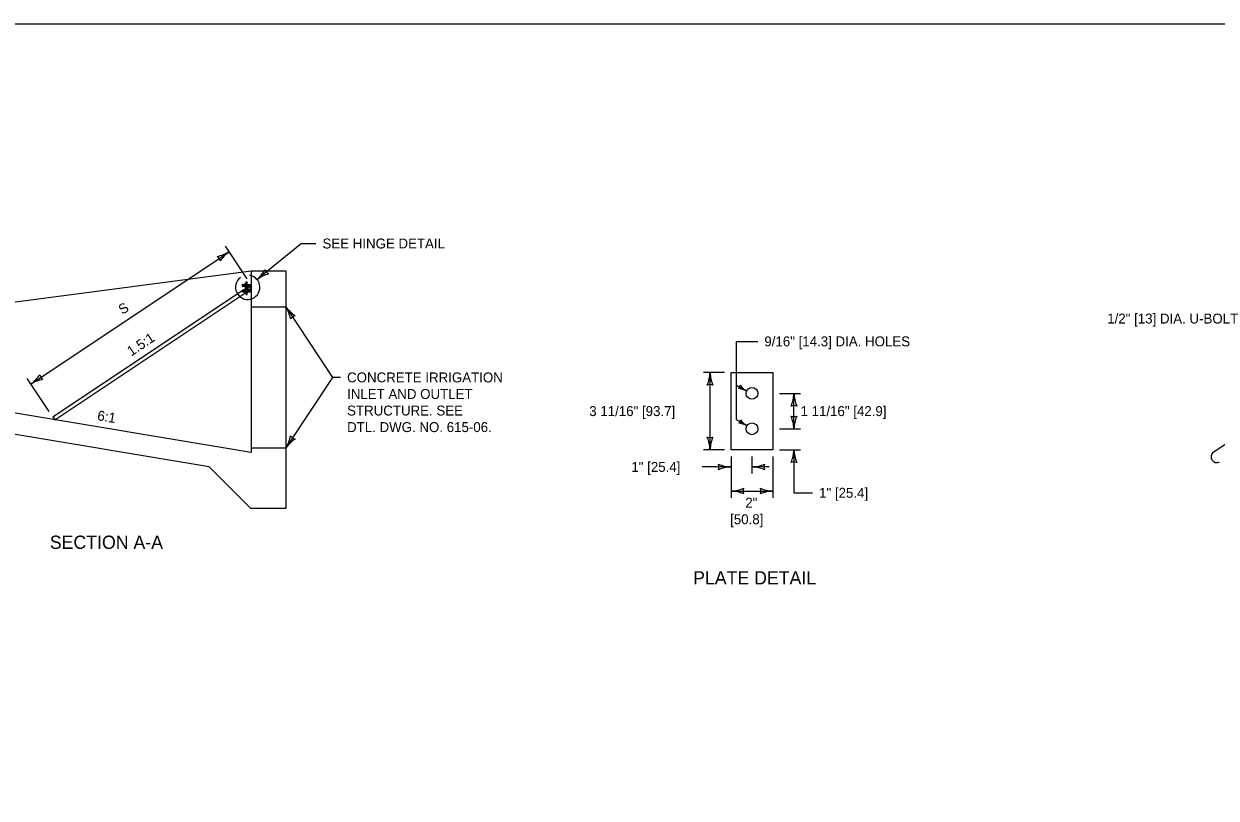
# Model space of a CAD drawing. Extents: x 49991.4 to 50021, y 49987.6 to 50011.4.
# Drawn here: x 50005.52 to 50012.72, y 49994.32 to 49999 of the extents above; entities that cross this region are included whole.
import ezdxf

# ---------------------------------------------------------------- set-up
doc = ezdxf.new("R2010")
doc.units = 0
for name, color, linetype in [('Level 1', 7, 'Continuous'), ('Level 2', 7, 'Continuous'), ('Level 3', 7, 'Continuous'), ('Level 4', 7, 'Continuous')]:
    doc.layers.add(name, color=color, linetype=linetype)

msp = doc.modelspace()

# ---------------------------------------------------------------- linework, layer by layer
at = {"layer": 'Level 1'}
for p, q in [((50005.12, 49997.2756), (50006.8919, 49997.5076)), ((50006.8919, 49997.5076), (50007.1028, 49997.5076)), ((50006.8919, 49997.5076), (50006.8919, 49996.4107)), ((50007.1028, 49997.5076), (50007.1028, 49996.0732)), ((50007.1028, 49997.5076), (50007.1028, 49996.0732)), ((50007.1028, 49997.5076), (50007.1028, 49996.0732)), ((50007.1028, 49997.5076), (50007.1028, 49996.0732)), ((50007.1028, 49997.5076), (50007.1028, 49996.0732)), ((50007.1028, 49997.5076), (50007.1028, 49996.0732)), ((50007.1028, 49997.5076), (50007.1028, 49996.0732)), ((50007.1028, 49997.5076), (50007.1028, 49996.0732)), ((50007.1028, 49997.5076), (50007.1028, 49996.0732)), ((50007.1028, 49997.5076), (50007.1028, 49996.0732)), ((50007.1028, 49997.5076), (50007.1028, 49996.0732)), ((50007.1028, 49997.5076), (50007.1028, 49996.0732)), ((50007.1028, 49997.5076), (50007.1028, 49996.0732)), ((50007.1028, 49997.5076), (50007.1028, 49996.0732)), ((50007.1028, 49997.5076), (50007.1028, 49996.0732)), ((50005.6946, 49996.6262), (50006.8391, 49997.3891)), ((50006.839, 49997.3902), (50006.8404, 49997.3916)), ((50006.839, 49997.3902), (50006.839, 49997.3825)), ((50006.8391, 49997.4246), (50006.8404, 49997.4259)), ((50006.8404, 49997.4259), (50006.8391, 49997.4246)), ((50006.8391, 49997.4246), (50006.8392, 49997.4167)), ((50006.8391, 49997.3891), (50006.8429, 49997.3916)), ((50006.8404, 49997.4259), (50006.8525, 49997.4259)), ((50006.8404, 49997.4259), (50006.8405, 49997.4154)), ((50006.8404, 49997.3916), (50006.8525, 49997.3916)), ((50006.8404, 49997.3916), (50006.8404, 49997.3811)), ((50006.8405, 49997.4154), (50006.8525, 49997.4154)), ((50006.8414, 49997.4246), (50006.8414, 49997.4167)), ((50006.8414, 49997.3902), (50006.8414, 49997.3825)), ((50006.8424, 49997.4259), (50006.8425, 49997.4154)), ((50006.8424, 49997.3916), (50006.8424, 49997.3811)), ((50006.8429, 49997.3916), (50006.8617, 49997.4041)), ((50006.8434, 49997.4246), (50006.8434, 49997.4167)), ((50006.8434, 49997.3902), (50006.8434, 49997.3825)), ((50006.8444, 49997.4259), (50006.8444, 49997.4154)), ((50006.8444, 49997.3916), (50006.8444, 49997.3811)), ((50006.8454, 49997.4246), (50006.8454, 49997.4167)), ((50006.8454, 49997.3902), (50006.8454, 49997.3825)), ((50006.8464, 49997.4259), (50006.8464, 49997.4154)), ((50006.8464, 49997.3916), (50006.8464, 49997.3811)), ((50006.8473, 49997.4246), (50006.8474, 49997.4167)), ((50006.8474, 49997.3902), (50006.8474, 49997.3825)), ((50006.8484, 49997.4259), (50006.8484, 49997.4154)), ((50006.8484, 49997.3916), (50006.8484, 49997.3811)), ((50006.8493, 49997.4246), (50006.8494, 49997.4167)), ((50006.8494, 49997.3825), (50006.8494, 49997.3902)), ((50006.8503, 49997.4259), (50006.8503, 49997.4154)), ((50006.8503, 49997.3916), (50006.8503, 49997.3811)), ((50006.8513, 49997.4246), (50006.8514, 49997.4167)), ((50006.8514, 49997.3825), (50006.8514, 49997.3902)), ((50006.8523, 49997.4259), (50006.8523, 49997.4154)), ((50006.8523, 49997.3916), (50006.8523, 49997.3811)), ((50006.8525, 49997.4149), (50006.8525, 49997.4268)), ((50006.8525, 49997.3799), (50006.8525, 49997.3926)), ((50006.8533, 49997.4298), (50006.8617, 49997.4298)), ((50006.8533, 49997.4246), (50006.8617, 49997.4246)), ((50006.8533, 49997.4167), (50006.8617, 49997.4167)), ((50006.8533, 49997.4114), (50006.8617, 49997.4114)), ((50006.8533, 49997.3956), (50006.8617, 49997.3956)), ((50006.8534, 49997.3903), (50006.8617, 49997.3903)), ((50006.8617, 49997.4035), (50006.8617, 49997.4424)), ((50006.8617, 49997.4424), (50006.8696, 49997.4424)), ((50006.8617, 49997.4114), (50006.8617, 49997.4298)), ((50006.8617, 49997.3646), (50006.8617, 49997.4035)), ((50006.8617, 49997.3771), (50006.8617, 49997.3956)), ((50006.8696, 49997.4035), (50006.8696, 49997.4424)), ((50006.8696, 49997.4259), (50006.8919, 49997.4259)), ((50006.8696, 49997.4154), (50006.8919, 49997.4154)), ((50006.8696, 49997.4093), (50006.8742, 49997.4124)), ((50006.8696, 49997.3646), (50006.8696, 49997.4035)), ((50006.8696, 49997.3916), (50006.8919, 49997.3916)), ((50006.8696, 49997.3916), (50006.8696, 49997.3811)), ((50006.8706, 49997.4247), (50006.8706, 49997.4168)), ((50006.8706, 49997.3904), (50006.8706, 49997.3825)), ((50006.8716, 49997.4259), (50006.8716, 49997.4154)), ((50006.8716, 49997.3916), (50006.8716, 49997.3811)), ((50006.8726, 49997.4247), (50006.8726, 49997.4168)), ((50006.8726, 49997.3904), (50006.8726, 49997.3825)), ((50006.8736, 49997.4259), (50006.8736, 49997.4154)), ((50006.8736, 49997.3916), (50006.8736, 49997.3811)), ((50006.8746, 49997.4247), (50006.8746, 49997.4168)), ((50006.8746, 49997.3904), (50006.8746, 49997.3825)), ((50006.8756, 49997.4259), (50006.8756, 49997.4154)), ((50006.8756, 49997.3916), (50006.8756, 49997.3811)), ((50006.8765, 49997.4247), (50006.8765, 49997.4168)), ((50006.8765, 49997.3904), (50006.8765, 49997.3825)), ((50006.8776, 49997.4259), (50006.8776, 49997.4154)), ((50006.8776, 49997.3916), (50006.8776, 49997.3811)), ((50006.8785, 49997.4247), (50006.8785, 49997.4168)), ((50006.8785, 49997.3904), (50006.8785, 49997.3825)), ((50006.8795, 49997.4259), (50006.8795, 49997.4154)), ((50006.8795, 49997.3916), (50006.8795, 49997.3811)), ((50006.8805, 49997.4247), (50006.8805, 49997.4168)), ((50006.8805, 49997.3904), (50006.8805, 49997.3825)), ((50006.8815, 49997.4259), (50006.8815, 49997.4154)), ((50006.8815, 49997.3916), (50006.8815, 49997.3811)), ((50006.8828, 49997.3916), (50006.886, 49997.3937)), ((50005.7066, 49996.6083), (50006.861, 49997.3771)), ((50006.8404, 49997.3811), (50006.8525, 49997.3811)), ((50006.8533, 49997.3824), (50006.8617, 49997.3824)), ((50006.8534, 49997.3771), (50006.8617, 49997.3771)), ((50006.8617, 49997.3646), (50006.8696, 49997.3646)), ((50006.8696, 49997.3811), (50006.8919, 49997.3811)), ((50009.7914, 49996.4276), (50009.7914, 49996.8942)), ((50009.7914, 49996.8942), (50010.0445, 49996.8942)), ((50010.0445, 49996.8942), (50010.0445, 49996.4276)), ((50012.7027, 49996.4127), (50013.4516, 49996.9119)), ((50006.8919, 49996.4107), (50005.12, 49996.7061)), ((50005.6946, 49996.6262), (50005.7066, 49996.6083)), ((50006.6385, 49996.3247), (50005.3431, 49996.5406)), ((50010.0445, 49996.4276), (50009.7914, 49996.4276)), ((50006.89, 49996.0732), (50006.6385, 49996.3247)), ((50007.1028, 49996.0732), (50006.89, 49996.0732))]:
    msp.add_line(p, q, dxfattribs=at)
msp.add_lwpolyline([(49999.3835, 49998.9992), (50016.7501, 49998.9992), (50016.7501, 49987.7988), (49999.3835, 49987.7988)], close=True, dxfattribs=at)
for points in [[(50006.8405, 49997.4154), (50006.8392, 49997.4167)], [(50006.8404, 49997.3811), (50006.839, 49997.3825)]]:
    msp.add_lwpolyline(points, dxfattribs=at)
for centre, radius in [((50006.8807, 49997.4035), 0.0111), ((50006.8807, 49997.4035), 0.00783), ((50009.918, 49996.7678), 0.0356), ((50009.918, 49996.5542), 0.0356)]:
    msp.add_circle(centre, radius, dxfattribs=at)
for centre, radius, start, end in [((50006.8571, 49997.414), 0.00461, 145.22217, 215.35597), ((50006.8571, 49997.4271), 0.00461, 145.43748, 214.03067), ((50006.8571, 49997.3929), 0.00461, 145.43748, 215.55565), ((50006.8686, 49997.4206), 0.0158, 165.34669, 194.2639), ((50006.8687, 49997.3863), 0.0158, 165.34669, 194.2639), ((50006.8571, 49997.3797), 0.00461, 145.22217, 215.3253), ((50012.7255, 49996.3857), 0.0353, 130.12517, 297.18147)]:
    msp.add_arc(centre, radius, start, end, dxfattribs=at)
at = {"layer": 'Level 2'}
msp.add_line((50007.4323, 49996.8643), (50007.384, 49996.8643), dxfattribs=at)
msp.add_lwpolyline([(50007.1028, 49997.2903), (50007.384, 49996.8643), (50007.1028, 49996.4382)], dxfattribs=at)
at = {"layer": 'Level 3'}
for p, q in [((50005.5626, 49996.8239), (50006.7599, 49997.6236)), ((50006.8697, 49997.4592), (50006.7377, 49997.6569)), ((50007.1972, 49997.6729), (50006.9289, 49997.4548)), ((50007.1972, 49997.6729), (50007.2835, 49997.6729)), ((50009.8226, 49997.0818), (50009.9526, 49997.0818)), ((50009.8226, 49997.0818), (50009.8226, 49996.6095)), ((50009.7514, 49996.8942), (50009.6248, 49996.8942)), ((50009.6648, 49996.4275), (50009.6648, 49996.8942)), ((50005.6724, 49996.6595), (50005.5403, 49996.8572)), ((50009.8226, 49996.818), (50009.8856, 49996.7827)), ((50010.0845, 49996.7677), (50010.2111, 49996.7677)), ((50010.1711, 49996.5541), (50010.1711, 49996.7677)), ((50009.8226, 49996.6095), (50009.8878, 49996.573)), ((50010.0845, 49996.5541), (50010.2111, 49996.5541)), ((50009.7514, 49996.4275), (50009.6248, 49996.4275)), ((50009.7914, 49996.3876), (50009.7914, 49996.1379)), ((50009.9179, 49996.3876), (50009.9179, 49996.2838)), ((50010.0445, 49996.3876), (50010.0445, 49996.1379)), ((50010.0845, 49996.4276), (50010.2111, 49996.4276)), ((50010.1711, 49996.4276), (50010.1711, 49996.1675)), ((50009.7914, 49996.3238), (50009.618, 49996.3238)), ((50010.0212, 49996.3238), (50009.9179, 49996.3238)), ((50009.7914, 49996.1779), (50010.0445, 49996.1779)), ((50010.1711, 49996.1675), (50010.2834, 49996.1675))]:
    msp.add_line(p, q, dxfattribs=at)
for centre, radius, start, end in [((50006.6441, 49997.8134), 0.2223, 281.19831, 301.38182), ((50006.8987, 49997.4365), 0.233, 126.56961, 145.81946), ((50006.6533, 49997.5524), 0.0548, 15.88112, 51.60348), ((50006.8719, 49997.4084), 0.0735, 126.75702, 80.01668), ((50006.7732, 49997.6281), 0.233, 311.93517, 331.18502), ((50007.0619, 49997.2766), 0.2223, 106.56387, 126.74738), ((50007.0284, 49997.5356), 0.0548, 201.24668, 236.96904), ((50006.9124, 49997.1756), 0.2223, 10.87741, 31.06092), ((50007.2907, 49997.4281), 0.233, 216.24871, 235.49856), ((50007.1734, 49997.1833), 0.0548, 105.56022, 141.28258), ((50009.4427, 49996.9034), 0.2223, 337.45601, 357.63952), ((50009.8975, 49996.9057), 0.233, 182.82731, 202.07716), ((50005.4237, 49997.011), 0.233, 306.57041, 325.82026), ((50005.6783, 49996.6341), 0.2223, 101.19911, 121.38262), ((50005.6692, 49996.8951), 0.0548, 195.88192, 231.60428), ((50009.6648, 49996.766), 0.0548, 72.13882, 107.86118), ((50009.8111, 49996.8245), 0.0365, 312.87615, 348.59851), ((50009.9634, 49996.9089), 0.1482, 218.19334, 238.37685), ((50009.8165, 49996.6436), 0.1553, 63.56464, 82.81449), ((50009.949, 49996.7769), 0.2223, 337.45601, 357.63952), ((50010.4038, 49996.7792), 0.233, 182.82731, 202.07716), ((50010.1711, 49996.6395), 0.0548, 72.13882, 107.86118), ((50009.8132, 49996.6148), 0.0365, 312.89802, 348.62038), ((50009.9654, 49996.6993), 0.1482, 218.21521, 238.39872), ((50010.1711, 49996.6823), 0.0548, 252.13882, 287.86118), ((50009.9384, 49996.5426), 0.233, 2.82731, 22.07716), ((50010.3933, 49996.545), 0.2223, 157.45601, 177.63952), ((50009.8187, 49996.4339), 0.1553, 63.58651, 82.83636), ((50006.9023, 49996.5568), 0.233, 329.40591, 348.65576), ((50007.2832, 49996.3082), 0.2223, 124.03461, 144.21812), ((50007.1734, 49996.5452), 0.0548, 218.71742, 254.43978), ((50009.6648, 49996.5557), 0.0548, 252.13882, 287.86118), ((50009.4321, 49996.416), 0.233, 2.82731, 22.07716), ((50009.887, 49996.4184), 0.2223, 157.45601, 177.63952), ((50009.949, 49996.4368), 0.2223, 337.45601, 357.63952), ((50010.4038, 49996.4391), 0.233, 182.82731, 202.07716), ((50009.8006, 49996.546), 0.2223, 247.45601, 267.63952), ((50009.6632, 49996.3238), 0.0548, 342.13882, 17.86118), ((50009.8029, 49996.0911), 0.233, 92.82731, 112.07716), ((50009.9064, 49996.5565), 0.233, 272.82731, 292.07716), ((50009.9088, 49996.1017), 0.2223, 67.45601, 87.63952), ((50010.0461, 49996.3238), 0.0548, 162.13882, 197.86118), ((50010.1711, 49996.2994), 0.0548, 72.13882, 107.86118), ((50009.7799, 49996.4106), 0.233, 272.82731, 292.07716), ((50009.7823, 49995.9558), 0.2223, 67.45601, 87.63952), ((50009.9196, 49996.1779), 0.0548, 162.13882, 197.86118), ((50010.0537, 49996.4), 0.2223, 247.45601, 267.63952), ((50009.9163, 49996.1779), 0.0548, 342.13882, 17.86118), ((50010.056, 49995.9452), 0.233, 92.82731, 112.07716)]:
    msp.add_arc(centre, radius, start, end, dxfattribs=at)
at = {"layer": 'Level 4'}
for p, q in [((50006.861, 49997.3771), (50006.8828, 49997.3916)), ((50006.8617, 49997.4259), (50006.8696, 49997.4259)), ((50006.8617, 49997.4154), (50006.8696, 49997.4154)), ((50006.8617, 49997.4041), (50006.8696, 49997.4093)), ((50006.8617, 49997.3916), (50006.8696, 49997.3916)), ((50006.8617, 49997.3811), (50006.8696, 49997.3811)), ((50006.8919, 49997.2903), (50007.1028, 49997.2903)), ((50006.8919, 49996.4382), (50007.1028, 49996.4382))]:
    msp.add_line(p, q, dxfattribs=at)

# ---------------------------------------------------------------- texts
at = {"layer": 'Level 2'}
for s, height, p in [('SEE HINGE DETAIL', 0.06, (50007.3235, 49997.6429)), ('1/2" [13] DIA. U-BOLT', 0.06, (50012.0637, 49997.1897)), ('9/16" [14.3] DIA. HOLES', 0.06, (50009.9926, 49997.052)), ('CONCRETE IRRIGATION', 0.06, (50007.4723, 49996.8343)), ('INLET AND OUTLET', 0.06, (50007.4723, 49996.7343)), ('STRUCTURE. SEE', 0.06, (50007.4723, 49996.6343)), ('3 11/16" [93.7]', 0.06, (50008.935, 49996.6309)), ('1 11/16" [42.9]', 0.06, (50010.2111, 49996.6309)), ('DTL. DWG. NO. 615-06.', 0.06, (50007.4723, 49996.5343)), ('1" [25.4]', 0.06, (50009.1894, 49996.2938)), ('1" [25.4]', 0.06, (50010.3234, 49996.1375)), ('2"', 0.06, (50009.8776, 49996.0779)), ('[50.8]', 0.06, (50009.7859, 49995.9779)), ('SECTION A-A', 0.08, (50005.6767, 49995.8291)), ('PLATE DETAIL', 0.08, (50009.5623, 49995.6144))]:
    msp.add_text(s, height=height, dxfattribs=at).set_placement(p)
for s, rotation, p in [('S', 33.69007, (50006.1159, 49997.2416)), ('1.5:1', 33.70233, (50006.1684, 49996.9901)), ('6:1', 350.56259, (50005.9603, 49996.6065))]:
    msp.add_text(s, height=0.06, rotation=rotation, dxfattribs=at).set_placement(p)

doc.saveas('drawing.dxf')
